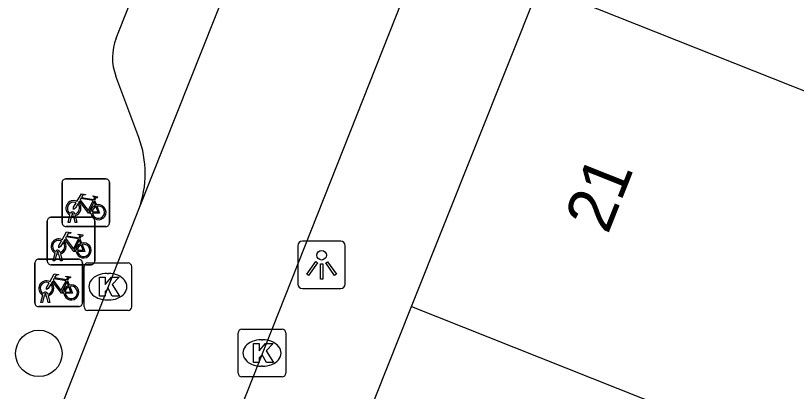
# Model space of a CAD drawing. Extents: x 161801 to 162379, y 382315 to 382832.
# Drawn here: x 162162.29 to 162178.73, y 382536.65 to 382544.56 of the extents above; entities that cross this region are included whole.
import ezdxf

# ---------------------------------------------------------------- set-up
doc = ezdxf.new("R2010")
doc.units = 0
for name, color, linetype in [('IMGEO_Boom', 7, 'Continuous'), ('IMGEO_Fietsenrek', 7, 'Continuous'), ('IMGEO_Kolk', 7, 'Continuous'), ('IMGEO_Lichtpunt', 7, 'Continuous'), ('IMGEO_Pand', 7, 'Continuous'), ('IMGEO_Pand_nummerreeks', 7, 'Continuous'), ('IMGEO_Rijbaan_lokaal_open', 7, 'Continuous'), ('IMGEO_Voetpad_open', 7, 'Continuous')]:
    doc.layers.add(name, color=color, linetype=linetype)

msp = doc.modelspace()

# ---------------------------------------------------------------- linework, layer by layer
at = {"layer": 'IMGEO_Boom'}
msp.add_circle((162162.779, 382537.446), 0.489, dxfattribs=at)
at = {"layer": 'IMGEO_Fietsenrek'}
for p, q in [((162163.267, 382540.195), (162163.267, 382541.036)), ((162163.267, 382541.036), (162163.267, 382540.195)), ((162163.342, 382541.12), (162164.183, 382541.12)), ((162164.183, 382541.12), (162163.342, 382541.12)), ((162164.267, 382541.045), (162164.267, 382540.204)), ((162164.267, 382540.204), (162164.267, 382541.045)), ((162163.954, 382540.669), (162163.99, 382540.574)), ((162163.031, 382540.314), (162163.872, 382540.314)), ((162163.872, 382540.314), (162163.031, 382540.314)), ((162163.394, 382540.204), (162163.433, 382540.364)), ((162163.463, 382540.352), (162163.428, 382540.204)), ((162163.505, 382540.376), (162163.504, 382540.38)), ((162163.546, 382540.204), (162163.512, 382540.346)), ((162163.536, 382540.387), (162163.537, 382540.38)), ((162163.544, 382540.35), (162163.579, 382540.204)), ((162162.956, 382539.389), (162162.956, 382540.23)), ((162162.956, 382540.23), (162162.956, 382539.389)), ((162163.428, 382540.204), (162163.394, 382540.204)), ((162163.579, 382540.204), (162163.546, 382540.204)), ((162163.956, 382540.239), (162163.956, 382539.398)), ((162163.956, 382539.398), (162163.956, 382540.239)), ((162164.192, 382540.12), (162163.351, 382540.12)), ((162163.351, 382540.12), (162164.192, 382540.12)), ((162163.643, 382539.863), (162163.679, 382539.768)), ((162163.083, 382539.398), (162163.122, 382539.558)), ((162163.152, 382539.546), (162163.117, 382539.398)), ((162163.194, 382539.57), (162163.193, 382539.574)), ((162163.235, 382539.398), (162163.201, 382539.54)), ((162163.225, 382539.581), (162163.226, 382539.574)), ((162163.233, 382539.544), (162163.268, 382539.398)), ((162162.696, 382538.506), (162162.696, 382539.347)), ((162162.696, 382539.347), (162162.696, 382538.506)), ((162162.771, 382539.431), (162163.612, 382539.431)), ((162163.612, 382539.431), (162162.771, 382539.431)), ((162163.881, 382539.314), (162163.04, 382539.314)), ((162163.04, 382539.314), (162163.881, 382539.314)), ((162163.117, 382539.398), (162163.083, 382539.398)), ((162163.268, 382539.398), (162163.235, 382539.398)), ((162163.696, 382539.356), (162163.696, 382538.515)), ((162163.696, 382538.515), (162163.696, 382539.356)), ((162163.383, 382538.98), (162163.419, 382538.885)), ((162162.823, 382538.515), (162162.862, 382538.675)), ((162162.892, 382538.663), (162162.857, 382538.515)), ((162162.934, 382538.687), (162162.933, 382538.691)), ((162162.975, 382538.515), (162162.941, 382538.657)), ((162162.965, 382538.698), (162162.966, 382538.691)), ((162162.973, 382538.661), (162163.008, 382538.515)), ((162162.857, 382538.515), (162162.823, 382538.515)), ((162163.008, 382538.515), (162162.975, 382538.515)), ((162163.621, 382538.431), (162162.78, 382538.431)), ((162162.78, 382538.431), (162163.621, 382538.431))]:
    msp.add_line(p, q, dxfattribs=at)
for points in [[(162163.58, 382540.646), (162163.675, 382540.81), (162163.761, 382540.796), (162163.763, 382540.787), (162163.707, 382540.776), (162163.68, 382540.731), (162163.936, 382540.69)], [(162163.876, 382540.402), (162163.826, 382540.402), (162163.635, 382540.653), (162163.616, 382540.621)], [(162163.923, 382540.665), (162163.666, 382540.706), (162163.649, 382540.677), (162163.816, 382540.457), (162163.923, 382540.665)], [(162163.971, 382540.567), (162163.941, 382540.644), (162163.832, 382540.426), (162163.875, 382540.426)], [(162163.936, 382540.69), (162163.961, 382540.739), (162163.955, 382540.743), (162163.932, 382540.747), (162163.92, 382540.754), (162163.919, 382540.757), (162163.921, 382540.762), (162164.016, 382540.747), (162164.018, 382540.737), (162164.008, 382540.724), (162163.996, 382540.718), (162163.982, 382540.724), (162163.954, 382540.669)], [(162163.601, 382540.594), (162163.549, 382540.504), (162163.509, 382540.479), (162163.51, 382540.526), (162163.565, 382540.62)], [(162163.905, 382540.426), (162164.025, 382540.425), (162163.981, 382540.539)], [(162164.001, 382540.546), (162164.056, 382540.401), (162163.906, 382540.401)], [(162163.269, 382539.84), (162163.364, 382540.004), (162163.45, 382539.99), (162163.452, 382539.981), (162163.396, 382539.97), (162163.369, 382539.925), (162163.625, 382539.884)], [(162163.29, 382539.788), (162163.238, 382539.698), (162163.198, 382539.673), (162163.199, 382539.72), (162163.254, 382539.814)], [(162163.565, 382539.596), (162163.515, 382539.596), (162163.324, 382539.847), (162163.305, 382539.815)], [(162163.612, 382539.859), (162163.355, 382539.9), (162163.338, 382539.871), (162163.505, 382539.651), (162163.612, 382539.859)], [(162163.66, 382539.761), (162163.63, 382539.838), (162163.521, 382539.62), (162163.564, 382539.62)], [(162163.625, 382539.884), (162163.65, 382539.933), (162163.644, 382539.937), (162163.621, 382539.941), (162163.609, 382539.948), (162163.608, 382539.951), (162163.61, 382539.956), (162163.705, 382539.941), (162163.707, 382539.931), (162163.697, 382539.918), (162163.685, 382539.912), (162163.671, 382539.918), (162163.643, 382539.863)], [(162163.594, 382539.62), (162163.714, 382539.619), (162163.67, 382539.733)], [(162163.69, 382539.74), (162163.745, 382539.595), (162163.595, 382539.595)], [(162163.009, 382538.957), (162163.104, 382539.121), (162163.19, 382539.107), (162163.192, 382539.098), (162163.136, 382539.087), (162163.109, 382539.042), (162163.365, 382539.001)], [(162163.352, 382538.976), (162163.095, 382539.017), (162163.078, 382538.988), (162163.245, 382538.768), (162163.352, 382538.976)], [(162163.365, 382539.001), (162163.39, 382539.05), (162163.384, 382539.054), (162163.361, 382539.058), (162163.349, 382539.065), (162163.348, 382539.068), (162163.35, 382539.073), (162163.445, 382539.058), (162163.447, 382539.048), (162163.437, 382539.035), (162163.425, 382539.029), (162163.411, 382539.035), (162163.383, 382538.98)], [(162163.03, 382538.905), (162162.978, 382538.815), (162162.938, 382538.79), (162162.939, 382538.837), (162162.994, 382538.931)], [(162163.305, 382538.713), (162163.255, 382538.713), (162163.064, 382538.964), (162163.045, 382538.932)], [(162163.4, 382538.878), (162163.37, 382538.955), (162163.261, 382538.737), (162163.304, 382538.737)], [(162163.334, 382538.737), (162163.454, 382538.736), (162163.41, 382538.85)], [(162163.43, 382538.857), (162163.485, 382538.712), (162163.335, 382538.712)]]:
    msp.add_lwpolyline(points, dxfattribs=at)
for centre, radius, start, end in [((162163.345, 382541.042), 0.0779, 92.4484, 184.2845), ((162163.345, 382541.042), 0.0779, 92.4484, 184.2845), ((162164.189, 382541.042), 0.0779, 2.4484, 94.2845), ((162164.189, 382541.042), 0.0779, 2.4484, 94.2845), ((162163.507, 382540.505), 0.159, 62.6766, 242.1369), ((162163.507, 382540.505), 0.129, 63.3192, 238.903), ((162163.507, 382540.505), 0.129, 283.6043, 43.4302), ((162163.507, 382540.505), 0.159, 283.5766, 46.6042), ((162164.034, 382540.421), 0.159, 113.3408, 178.3217), ((162164.034, 382540.421), 0.159, 187.0065, 105.7708), ((162164.034, 382540.421), 0.129, 113.923, 177.9556), ((162164.034, 382540.421), 0.129, 188.6715, 104.5883), ((162163.034, 382540.236), 0.0779, 92.4484, 184.2845), ((162163.034, 382540.236), 0.0779, 92.4484, 184.2845), ((162163.487, 382540.376), 0.0499, 12.8025, 158.6934), ((162163.507, 382540.505), 0.159, 253.9967, 271.7867), ((162163.487, 382540.376), 0.0174, 12.8025, 163.4502), ((162163.507, 382540.505), 0.129, 253.415, 269.0204), ((162163.878, 382540.236), 0.0779, 2.4484, 94.2845), ((162163.878, 382540.236), 0.0779, 2.4484, 94.2845), ((162163.345, 382540.198), 0.0779, 182.4484, 274.2845), ((162163.345, 382540.198), 0.0779, 182.4484, 274.2845), ((162164.189, 382540.198), 0.0779, 272.4484, 4.2845), ((162164.189, 382540.198), 0.0779, 272.4484, 4.2845), ((162163.196, 382539.699), 0.159, 62.6766, 242.1369), ((162163.196, 382539.699), 0.129, 63.3192, 238.903), ((162163.196, 382539.699), 0.159, 283.5766, 46.6042), ((162163.196, 382539.699), 0.129, 283.6043, 43.4302), ((162163.723, 382539.615), 0.159, 113.3408, 178.3217), ((162163.723, 382539.615), 0.159, 187.0065, 105.7708), ((162163.723, 382539.615), 0.129, 113.923, 177.9556), ((162163.723, 382539.615), 0.129, 188.6715, 104.5883), ((162163.176, 382539.57), 0.0499, 12.8025, 158.6934), ((162163.196, 382539.699), 0.159, 253.9967, 271.7867), ((162163.176, 382539.57), 0.0174, 12.8025, 163.4502), ((162163.196, 382539.699), 0.129, 253.415, 269.0204), ((162162.774, 382539.353), 0.0779, 92.4484, 184.2845), ((162162.774, 382539.353), 0.0779, 92.4484, 184.2845), ((162163.034, 382539.392), 0.0779, 182.4484, 274.2845), ((162163.034, 382539.392), 0.0779, 182.4484, 274.2845), ((162163.618, 382539.353), 0.0779, 2.4484, 94.2845), ((162163.618, 382539.353), 0.0779, 2.4484, 94.2845), ((162163.878, 382539.392), 0.0779, 272.4484, 4.2845), ((162163.878, 382539.392), 0.0779, 272.4484, 4.2845), ((162162.936, 382538.816), 0.159, 62.6766, 242.1369), ((162162.936, 382538.816), 0.129, 63.3192, 238.903), ((162162.936, 382538.816), 0.129, 283.6043, 43.4302), ((162162.936, 382538.816), 0.159, 283.5766, 46.6042), ((162163.463, 382538.732), 0.159, 113.3408, 178.3217), ((162163.463, 382538.732), 0.159, 187.0065, 105.7708), ((162163.463, 382538.732), 0.129, 113.923, 177.9556), ((162163.463, 382538.732), 0.129, 188.6715, 104.5883), ((162162.916, 382538.687), 0.0499, 12.8025, 158.6934), ((162162.936, 382538.816), 0.159, 253.9967, 271.7867), ((162162.916, 382538.687), 0.0174, 12.8025, 163.4502), ((162162.936, 382538.816), 0.129, 253.415, 269.0204), ((162162.774, 382538.509), 0.0779, 182.4484, 274.2845), ((162162.774, 382538.509), 0.0779, 182.4484, 274.2845), ((162163.618, 382538.509), 0.0779, 272.4484, 4.2845), ((162163.618, 382538.509), 0.0779, 272.4484, 4.2845)]:
    msp.add_arc(centre, radius, start, end, dxfattribs=at)
at = {"layer": 'IMGEO_Kolk'}
for p, q in [((162163.807, 382539.351), (162164.659, 382539.351)), ((162163.732, 382538.425), (162163.732, 382539.277)), ((162164.733, 382539.277), (162164.733, 382538.425)), ((162164.22, 382539.131), (162164.245, 382539.131)), ((162164.243, 382538.571), (162164.218, 382538.571)), ((162164.659, 382538.351), (162163.807, 382538.351)), ((162166.976, 382537.028), (162166.976, 382537.88)), ((162167.051, 382537.954), (162167.903, 382537.954)), ((162167.977, 382537.88), (162167.977, 382537.028)), ((162167.464, 382537.734), (162167.489, 382537.734)), ((162167.487, 382537.174), (162167.462, 382537.174)), ((162167.903, 382536.954), (162167.051, 382536.954))]:
    msp.add_line(p, q, dxfattribs=at)
for points in [[(162163.807, 382539.351), (162164.659, 382539.351)], [(162163.732, 382538.425), (162163.732, 382539.277)], [(162164.733, 382539.277), (162164.733, 382538.425)], [(162164.053, 382539.051), (162164.176, 382539.051), (162164.176, 382538.9), (162164.306, 382539.051), (162164.47, 382539.051), (162164.324, 382538.9), (162164.477, 382538.651), (162164.325, 382538.651), (162164.24, 382538.815), (162164.176, 382538.748), (162164.176, 382538.651), (162164.053, 382538.651), (162164.053, 382539.051)], [(162164.659, 382538.351), (162163.807, 382538.351)], [(162166.976, 382537.028), (162166.976, 382537.88)], [(162167.051, 382537.954), (162167.903, 382537.954)], [(162167.977, 382537.88), (162167.977, 382537.028)], [(162167.297, 382537.654), (162167.42, 382537.654), (162167.42, 382537.503), (162167.55, 382537.654), (162167.714, 382537.654), (162167.568, 382537.503), (162167.721, 382537.254), (162167.569, 382537.254), (162167.484, 382537.418), (162167.42, 382537.351), (162167.42, 382537.254), (162167.297, 382537.254), (162167.297, 382537.654)], [(162167.903, 382536.954), (162167.051, 382536.954)]]:
    msp.add_lwpolyline(points, dxfattribs=at)
for centre, start, end in [((162163.809, 382539.275), 91.552, 178.448), ((162163.809, 382539.275), 91.552, 178.448), ((162164.657, 382539.275), 1.552, 88.448), ((162164.657, 382539.275), 1.552, 88.448), ((162163.809, 382538.427), 181.552, 268.448), ((162163.809, 382538.427), 181.552, 268.448), ((162164.657, 382538.427), 271.552, 358.448), ((162164.657, 382538.427), 271.552, 358.448), ((162167.053, 382537.878), 91.552, 178.448), ((162167.053, 382537.878), 91.552, 178.448), ((162167.901, 382537.878), 1.552, 88.448), ((162167.901, 382537.878), 1.552, 88.448), ((162167.053, 382537.03), 181.552, 268.448), ((162167.053, 382537.03), 181.552, 268.448), ((162167.901, 382537.03), 271.552, 358.448), ((162167.901, 382537.03), 271.552, 358.448)]:
    msp.add_arc(centre, 0.0765, start, end, dxfattribs=at)
for centre, major_axis, ratio, start_param, end_param in [((162164.219, 382538.851), (-0.387, 0.002), 0.722429, 4.712389, 7.853982), ((162164.244, 382538.851), (-0.39, 0.002), 0.717154, 1.570796, 4.712389), ((162167.463, 382537.454), (-0.387, 0.002), 0.722429, 4.712389, 7.853982), ((162167.488, 382537.454), (-0.39, 0.002), 0.717154, 1.570796, 4.712389)]:
    msp.add_ellipse(centre, major_axis=major_axis, ratio=ratio, start_param=start_param, end_param=end_param, dxfattribs=at)
at = {"layer": 'IMGEO_Lichtpunt'}
for p, q in [((162169.136, 382539.81), (162168.328, 382539.81)), ((162169.136, 382539.81), (162168.328, 382539.81)), ((162168.234, 382539.715), (162168.234, 382538.908)), ((162168.234, 382539.715), (162168.234, 382538.908)), ((162169.23, 382538.908), (162169.23, 382539.715)), ((162169.23, 382538.908), (162169.23, 382539.715)), ((162168.328, 382538.814), (162169.136, 382538.814)), ((162168.328, 382538.814), (162169.136, 382538.814))]:
    msp.add_line(p, q, dxfattribs=at)
for points in [[(162168.608, 382539.379), (162168.647, 382539.351), (162168.459, 382539.089), (162168.421, 382539.116), (162168.608, 382539.379)], [(162168.71, 382539.331), (162168.757, 382539.331), (162168.757, 382539.009), (162168.71, 382539.009), (162168.71, 382539.331)], [(162168.82, 382539.351), (162168.858, 382539.378), (162169.045, 382539.116), (162169.006, 382539.088), (162168.82, 382539.351)]]:
    msp.add_lwpolyline(points, dxfattribs=at)
msp.add_circle((162168.733, 382539.513), 0.0994, dxfattribs=at)
for centre, start, end in [((162168.328, 382539.715), 90, 180), ((162168.328, 382539.715), 90, 180), ((162169.136, 382539.715), 0, 90), ((162169.136, 382539.715), 0, 90), ((162168.328, 382538.908), 180, 270), ((162168.328, 382538.908), 180, 270), ((162169.136, 382538.908), 270, 0), ((162169.136, 382538.908), 270, 360)]:
    msp.add_arc(centre, 0.0946, start, end, dxfattribs=at)
at = {"layer": 'IMGEO_Pand'}
for points in [[(162170.627, 382538.431), (162173.318, 382545.194)], [(162173.318, 382545.194), (162178.647, 382543.075), (162180.788, 382542.223), (162182.61, 382541.498), (162181.649, 382539.082), (162182.578, 382538.713), (162183.15, 382535.817), (162182.349, 382535.566)], [(162169.14, 382534.691), (162170.627, 382538.431)], [(162170.627, 382538.431), (162179.823, 382534.773), (162182.349, 382535.566)]]:
    msp.add_lwpolyline(points, dxfattribs=at)
at = {"layer": 'IMGEO_Rijbaan_lokaal_open'}
for points in [[(162164.884, 382540.483), (162170.508, 382554.627)], [(162171.513, 382547.64), (162166.587, 382535.18)], [(162163.254, 382536.338), (162164.884, 382540.483)]]:
    msp.add_lwpolyline(points, dxfattribs=at)
at = {"layer": 'IMGEO_Voetpad_open'}
for points in [[(162164.408, 382544.086), (162167.97, 382553.061)], [(162164.883, 382541.996), (162164.4, 382543.285)]]:
    msp.add_lwpolyline(points, dxfattribs=at)
for centre, radius, start, end in [((162165.436, 382543.675), 1.107, 158.2151, 200.6405), ((162162.839, 382541.238), 2.18, 339.7282, 20.3475)]:
    msp.add_arc(centre, radius, start, end, dxfattribs=at)

# ---------------------------------------------------------------- texts
at = {"layer": 'IMGEO_Pand_nummerreeks'}
msp.add_text('21', height=1, rotation=68.3023, dxfattribs=at).set_placement((162174.756, 382539.936))

doc.saveas('drawing.dxf')
